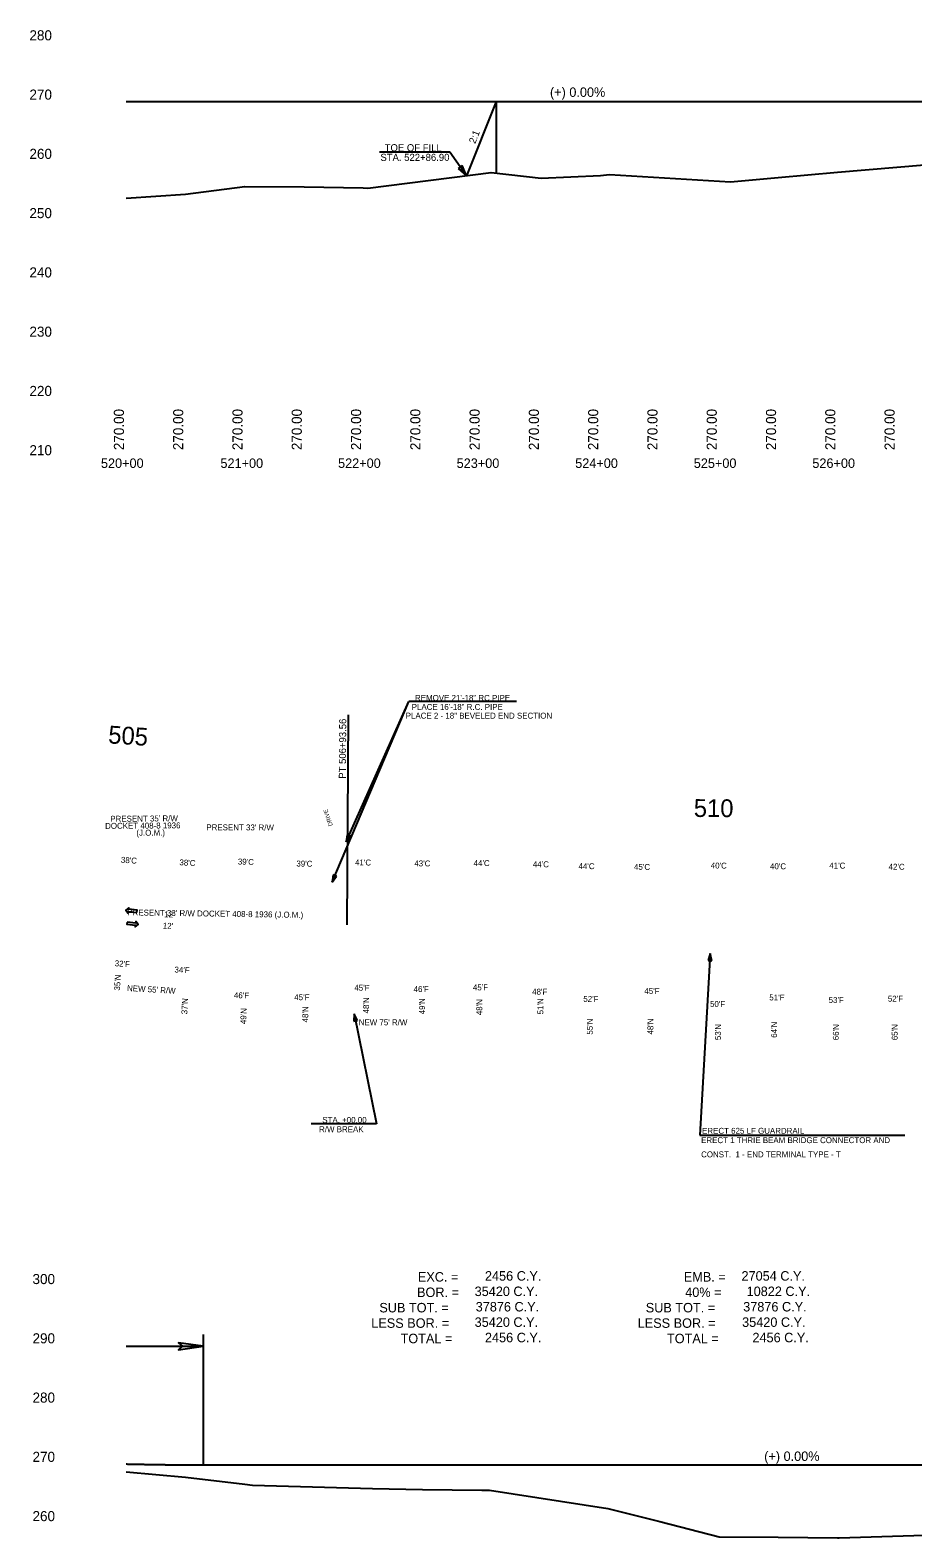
# Model space of a CAD drawing. Extents: x 48556 to 51363, y 45290 to 53458.
# Drawn here: x 49107 to 49851, y 48061 to 49333 of the extents above; entities that cross this region are included whole.
import ezdxf

# ---------------------------------------------------------------- set-up
doc = ezdxf.new("R2010")
doc.units = 0
for name, color, linetype in [('Level 1', 7, 'Continuous'), ('Level 14', 7, 'Continuous'), ('Level 19', 7, 'Continuous'), ('Level 20', 7, 'Continuous'), ('Level 24', 7, 'Continuous'), ('Level 27', 7, 'Continuous'), ('Level 29', 7, 'Continuous'), ('Level 33', 7, 'Continuous'), ('Level 40', 7, 'Continuous'), ('Level 41', 7, 'Continuous'), ('Level 42', 7, 'Continuous'), ('Level 43', 7, 'Continuous'), ('Level 45', 7, 'Continuous'), ('Level 48', 7, 'Continuous'), ('Level 6', 7, 'Continuous'), ('Level 8', 7, 'Continuous')]:
    doc.layers.add(name, color=color, linetype=linetype)

msp = doc.modelspace()

# ---------------------------------------------------------------- linework, layer by layer
at = {"layer": 'Level 1'}
msp.add_lwpolyline([(49252.9, 48222.9), (49232.1, 48225.8), (49235.3, 48222.9), (49232.1, 48219.9)], close=True, dxfattribs=at)
at = {"layer": 'Level 14'}
for points in [[(49197, 48588.9), (49197.2, 48590.8), (49189.9, 48591.6), (49190, 48592.8), (49187.5, 48590.8), (49189.5, 48588.3), (49189.7, 48589.6)], [(49188.7, 48580.8), (49188.5, 48578.9), (49195.8, 48578.1), (49195.6, 48576.8), (49198.1, 48578.8), (49196.1, 48581.3), (49196, 48580)]]:
    msp.add_lwpolyline(points, close=True, dxfattribs=at)
at = {"layer": 'Level 19'}
msp.add_line((49374.2, 48578.4), (49375.4, 48755.6), dxfattribs=at)
at = {"layer": 'Level 24'}
for p, q in [((49471.4, 49219.1), (49467.8, 49216.5)), ((49467.8, 49216.5), (49474.8, 49210.4)), ((49474.8, 49210.4), (49471.4, 49219.1)), ((49374.4, 48654.5), (49373.4, 48648.4)), ((49373.4, 48648.4), (49377.2, 48653.3)), ((49377.2, 48653.3), (49374.4, 48654.5)), ((49362.6, 48620.5), (49361.6, 48614.4)), ((49361.6, 48614.4), (49365.4, 48619.4)), ((49365.4, 48619.4), (49362.6, 48620.5)), ((49680.5, 48554.2), (49678.7, 48548.3)), ((49678.7, 48548.3), (49681.7, 48548.1)), ((49681.7, 48548.1), (49680.5, 48554.2)), ((49380.2, 48503.4), (49379.9, 48497.2)), ((49379.9, 48497.2), (49382.9, 48497.8)), ((49382.9, 48497.8), (49380.2, 48503.4))]:
    msp.add_line(p, q, dxfattribs=at)
at = {"layer": 'Level 27'}
for p, q in [((49680.5, 48554.2), (49671.6, 48401.1)), ((49671.6, 48401.1), (49844.7, 48401.1))]:
    msp.add_line(p, q, dxfattribs=at)
at = {"layer": 'Level 33'}
for p, q in [((49380.2, 48503.4), (49399.1, 48410.6)), ((49399.1, 48410.6), (49344, 48410.6))]:
    msp.add_line(p, q, dxfattribs=at)
at = {"layer": 'Level 40'}
for points in [[(49187.9, 49191.5), (49237.9, 49194.9), (49287.9, 49201.4), (49337.9, 49200.9), (49387.9, 49200.1), (49391.8, 49200), (49495.7, 49213), (49537.9, 49208.2), (49587.9, 49210.7), (49595.6, 49211.5), (49697.6, 49205.2), (49737.9, 49208.8), (49787.9, 49213.5), (49837.9, 49217.7), (49887.9, 49221.7)], [(49187.9, 48117.1), (49237.9, 48112.6), (49287.9, 48106.7), (49294.5, 48105.9), (49395.5, 48102.9), (49437.9, 48102.2), (49487.9, 48101.6), (49494.3, 48101.6), (49594.2, 48086.2), (49637.9, 48075), (49687.9, 48062.1), (49737.9, 48061.9), (49787.9, 48061.3), (49789.2, 48061.3), (49897.1, 48064.8)]]:
    msp.add_lwpolyline(points, dxfattribs=at)
at = {"layer": 'Level 41'}
for p, q in [((49252.9, 48232.9), (49252.9, 48122.9)), ((49187.9, 48222.9), (49252.9, 48222.9))]:
    msp.add_line(p, q, dxfattribs=at)
at = {"layer": 'Level 45'}
for p, q in [((49187.9, 49272.9), (49499.9, 49272.9)), ((49499.9, 49272.9), (49474.8, 49210.4)), ((49499.9, 49272.9), (49499.9, 49212.5)), ((49499.9, 49272.9), (50687.9, 49272.9)), ((49460.8, 49230.2), (49401.4, 49230.2)), ((49474.8, 49210.4), (49460.8, 49230.2)), ((49252.9, 48122.9), (50399.9, 48122.9))]:
    msp.add_line(p, q, dxfattribs=at)
msp.add_spline([(49187.9, 48123.7), (49189.2, 48123.6), (49190.5, 48123.6), (49191.8, 48123.6), (49193.1, 48123.6), (49194.4, 48123.5), (49195.7, 48123.5), (49197, 48123.5), (49198.3, 48123.4), (49199.6, 48123.4), (49200.9, 48123.4), (49202.2, 48123.4), (49203.5, 48123.3), (49204.8, 48123.3), (49206.1, 48123.3), (49207.4, 48123.3), (49208.7, 48123.2), (49210, 48123.2), (49211.3, 48123.2), (49212.6, 48123.2), (49213.9, 48123.2), (49215.2, 48123.1), (49216.5, 48123.1), (49217.8, 48123.1), (49219.1, 48123.1), (49220.4, 48123.1), (49221.7, 48123), (49223, 48123), (49224.3, 48123), (49225.6, 48123), (49226.9, 48123), (49228.2, 48123), (49229.5, 48123), (49230.8, 48122.9), (49232.1, 48122.9), (49233.4, 48122.9), (49234.7, 48122.9), (49236, 48122.9), (49237.3, 48122.9), (49238.6, 48122.9), (49239.9, 48122.9), (49241.2, 48122.9), (49242.5, 48122.9), (49243.8, 48122.9), (49245.1, 48122.9), (49246.4, 48122.9), (49247.7, 48122.9), (49249, 48122.9), (49250.3, 48122.9), (49251.6, 48122.9), (49252.9, 48122.9)], degree=3, dxfattribs=at)
at = {"layer": 'Level 6'}
for p in [(49361.6, 48614.4), (49373.4, 48648.4), (49517.2, 48766.9)]:
    msp.add_line(p, (49426.3, 48766.9), dxfattribs=at)

# ---------------------------------------------------------------- texts
at = {"layer": 'Level 1'}
for s, rotation, p in [(' DOCKET 408-8 1936 ', 0.4075, (49168.3, 48659.4)), ("PRESENT 35' R/W", 0.4075, (49174.5, 48665.4)), ("PRESENT 33' R/W ", 359.8723, (49255.5, 48658.2)), ('(J.O.M.)', 0.4075, (49196.5, 48653.6)), ("PRESENT 33' R/W DOCKET 408-8 1936 (J.O.M.)", 359.1607, (49188.8, 48586.5))]:
    msp.add_text(s, height=5, rotation=rotation, dxfattribs=at).set_placement(p)
for s, p in [('EXC. =', (49433.9, 48277.5)), (' 2456 C.Y.', (49487.5, 48278.3)), ('EMB. =', (49658.2, 48277.5)), (' 27054 C.Y.', (49703.9, 48278.3)), ('BOR. =', (49433.2, 48264.5)), (' 35420 C.Y.', (49478.8, 48265.3)), ('40% =', (49659.4, 48264.5)), (' 10822 C.Y.', (49708.2, 48265.3)), ('SUB TOT. =', (49401.4, 48251.5)), (' 37876 C.Y.', (49479.7, 48252.3)), ('SUB TOT. =', (49626.1, 48251.5)), (' 37876 C.Y.', (49705.3, 48252.3)), ('LESS BOR. =', (49394.6, 48238.5)), (' 35420 C.Y.', (49478.8, 48239.3)), ('LESS BOR. =', (49619.3, 48238.5)), (' 35420 C.Y.', (49704.4, 48239.3)), ('TOTAL =', (49419.3, 48225.5)), (' 2456 C.Y.', (49487.5, 48226.3)), ('TOTAL =', (49644, 48225.5)), (' 2456 C.Y.', (49713.1, 48226.3))]:
    msp.add_text(s, height=8, dxfattribs=at).set_placement(p)
at = {"layer": 'Level 19'}
for s, height, rotation, p in [('PT 506+93.56', 6, 89.6334, (49373.2, 48701.7)), ('505', 15, 356.2461, (49172.4, 48731.6)), ('510', 15, 359.6334, (49666.6, 48669.5))]:
    msp.add_text(s, height=height, rotation=rotation, dxfattribs=at).set_placement(p)
at = {"layer": 'Level 20'}
for p in [(49219.9, 48584.9), (49218.7, 48575.3)]:
    msp.add_text("12'", height=5, rotation=357.8501, dxfattribs=at).set_placement(p)
at = {"layer": 'Level 27'}
for s, p in [('ERECT 1 THRIE BEAM BRIDGE CONNECTOR AND ', (49672.8, 48394.3)), ('ERECT 625 LF GUARDRAIL', (49673.6, 48402.2)), ('CONST.  1 - END TERMINAL TYPE - T', (49672.8, 48382.3))]:
    msp.add_text(s, height=5, dxfattribs=at).set_placement(p)
at = {"layer": 'Level 29'}
for s, p in [('PLACE 16\'-18" R.C. PIPE', (49428.7, 48759.8)), (' PLACE 2 - 18" BEVELED END SECTION', (49421.8, 48752.4))]:
    msp.add_text(s, height=5, dxfattribs=at).set_placement(p)
at = {"layer": 'Level 33'}
for s, rotation, p in [("NEW 55' R/W", 356.5816, (49188.5, 48522.7)), ("NEW 75' R/W", 359.7811, (49384, 48493.8))]:
    msp.add_text(s, height=5, rotation=rotation, dxfattribs=at).set_placement(p)
for s, p in [('R/W BREAK', (49350.6, 48403.5)), ('STA. +00.00', (49353.3, 48411.4))]:
    msp.add_text(s, height=5, dxfattribs=at).set_placement(p)
at = {"layer": 'Level 41'}
for p in [(49545.3, 49276.9), (49726, 48126.2)]:
    msp.add_text('(+) 0.00%', height=8, dxfattribs=at).set_placement(p)
at = {"layer": 'Level 42'}
for s, height, p in [('280', 8.5, (49106.3, 49324.6)), ('270', 8.5, (49106.3, 49274.6)), ('260', 8.5, (49106.3, 49224.6)), ('250', 8.5, (49106.3, 49174.6)), ('240', 8.5, (49106.3, 49124.6)), ('230', 8.5, (49106.3, 49074.6)), ('220', 8.5, (49106.3, 49024.6)), ('210', 8.5, (49106.3, 48974.6)), ('520+00', 8, (49166.6, 48963.9)), ('521+00', 8, (49267.4, 48963.9)), ('522+00', 8, (49366.6, 48963.9)), ('523+00', 8, (49466.6, 48963.9)), ('524+00', 8, (49566.6, 48963.9)), ('525+00', 8, (49666.6, 48963.9)), ('526+00', 8, (49766.6, 48963.9)), ('300', 8.5, (49108.9, 48275.4)), ('290', 8.5, (49108.9, 48225.4)), ('280', 8.5, (49108.9, 48175.4)), ('270', 8.5, (49108.9, 48125.4)), ('260', 8.5, (49108.9, 48075.4))]:
    msp.add_text(s, height=height, dxfattribs=at).set_placement(p)
at = {"layer": 'Level 43'}
for p in [(49186, 48978.9), (49236, 48978.9), (49286, 48978.9), (49336, 48978.9), (49386, 48978.9), (49436, 48978.9), (49486, 48978.9), (49536, 48978.9), (49586, 48978.9), (49636, 48978.9), (49686, 48978.9), (49736, 48978.9), (49786, 48978.9), (49836, 48978.9)]:
    msp.add_text('270.00', height=8.5, rotation=90, dxfattribs=at).set_placement(p)
at = {"layer": 'Level 45'}
msp.add_text('2:1', height=6, rotation=68.0994, dxfattribs=at).set_placement((49482.2, 49236.9))
for s, p in [('TOE OF FILL ', (49405.9, 49231)), ('STA. 522+86.90', (49402.3, 49222.9))]:
    msp.add_text(s, height=6, dxfattribs=at).set_placement(p)
at = {"layer": 'Level 48'}
for s, rotation, p in [("38'C", 356.2461, (49183.3, 48630.9)), ("38'C", 357.1211, (49232.7, 48628.7)), ("39'C", 357.9961, (49282, 48629.4)), ("39'C", 358.8711, (49331.4, 48627.7)), ("41'C", 359.6334, (49380.9, 48628.6)), ("43'C", 359.6334, (49430.9, 48627.8)), ("44'C", 359.6334, (49480.9, 48628.1)), ("44'C", 359.6334, (49530.9, 48627.1)), ("44'C", 359.6334, (49569.4, 48625.5)), ("45'C", 359.6334, (49616.2, 48624.9)), ("40'C", 359.6334, (49680.9, 48626)), ("40'C", 359.6334, (49730.9, 48625.4)), ("41'C", 359.6334, (49780.9, 48626)), ("42'C", 359.6334, (49830.9, 48625)), ("32'F", 356.2461, (49178.1, 48543.6)), ("35'N", 86.2461, (49182.6, 48522.9)), ("34'F", 357.1211, (49228.5, 48538.3)), ("45'F", 359.6334, (49380.3, 48522.9)), ("46'F", 359.6334, (49430.3, 48521.8)), ("45'F", 359.6333, (49480.3, 48523.2)), ("48'F", 359.6334, (49530.3, 48519.6)), ("45'F", 359.6334, (49624.9, 48520.2)), ("37'N", 87.1211, (49239.4, 48502.9)), ("46'F", 357.9961, (49278.7, 48516.7)), ("45'F", 358.8711, (49329.6, 48515)), ("48'N", 89.6334, (49392.7, 48503.7)), ("49'N", 89.6334, (49439.9, 48503)), ("48'N", 89.6333, (49488.2, 48502.2)), ("51'N", 89.6334, (49539.7, 48502.9)), ("52'F", 359.6334, (49573.4, 48513.5)), ("50'F", 359.6334, (49680.3, 48509.2)), ("51'F", 359.6334, (49730.3, 48514.7)), ("53'F", 359.6333, (49780.3, 48512.6)), ("52'F", 359.6334, (49830.3, 48513.7)), ("49'N", 87.9961, (49289.1, 48494.6)), ("48'N", 88.8711, (49341.3, 48496.1)), ("55'N", 89.6334, (49581.4, 48485.8)), ("48'N", 89.6334, (49632.5, 48485.9)), ("53'N", 89.6334, (49689.5, 48481.2)), ("64'N", 89.6334, (49736.8, 48483.2)), ("66'N", 89.6333, (49788.9, 48481.1)), ("65'N", 89.6334, (49838.5, 48481.1))]:
    msp.add_text(s, height=5, rotation=rotation, dxfattribs=at).set_placement(p)
at = {"layer": 'Level 6'}
msp.add_text('REMOVE 21\'-18" RC PIPE', height=5, dxfattribs=at).set_placement((49431.5, 48767.4))
at = {"layer": 'Level 8'}
msp.add_text('DRIVE', height=3.5, rotation=108.8976, dxfattribs=at).set_placement((49362.2, 48662.4))

doc.saveas('drawing.dxf')
